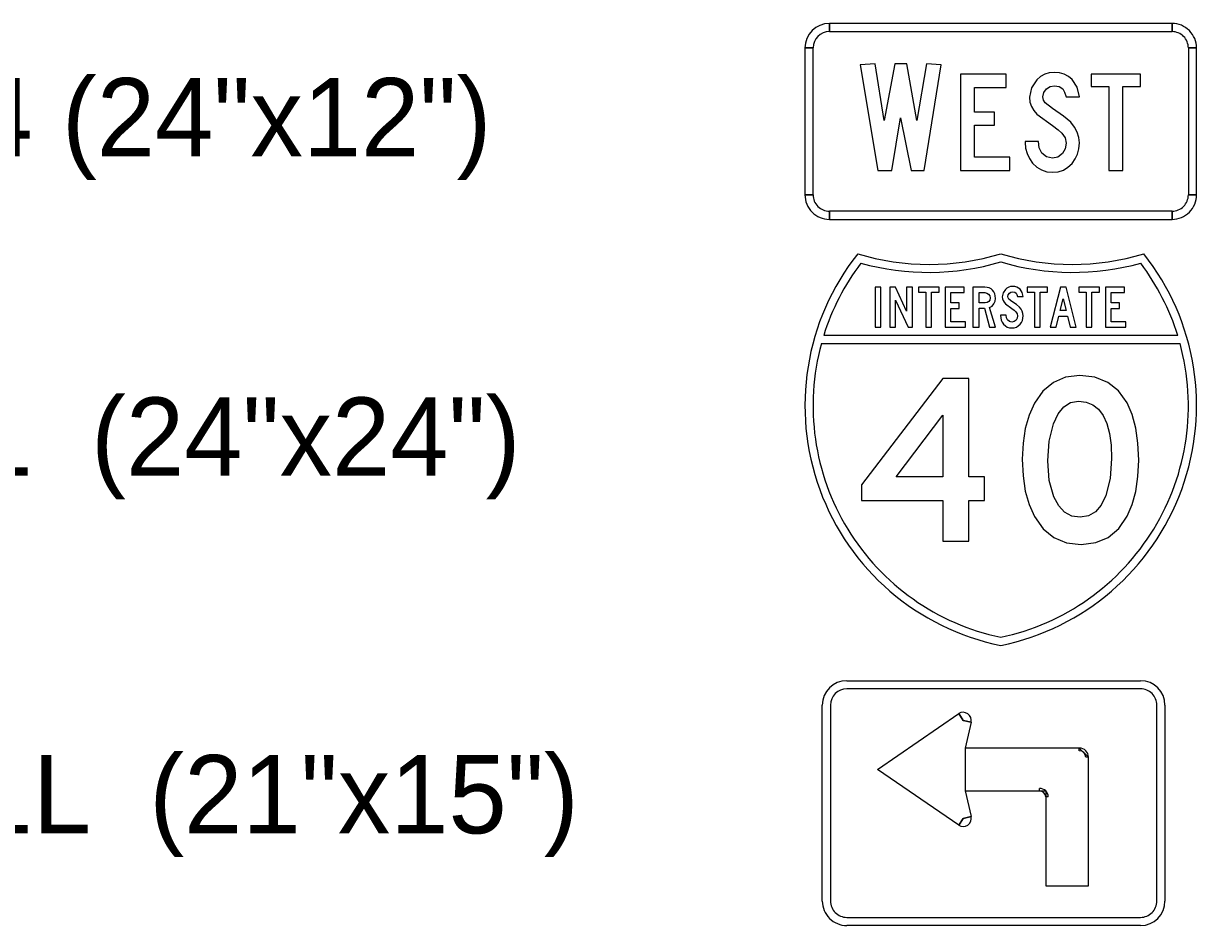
# Model space of a CAD drawing. Extents: x 620864 to 620948.6, y 415499.7 to 415559.1.
# Drawn here: x 620904.04 to 620910.03, y 415510.88 to 415515.48 of the extents above; entities that cross this region are included whole.
import ezdxf

# ---------------------------------------------------------------- set-up
doc = ezdxf.new("R2010")
doc.units = 0
doc.layers.add('SIGNS', color=7, linetype='Continuous')

msp = doc.modelspace()

# ---------------------------------------------------------------- linework, layer by layer
at = {"layer": 'SIGNS'}
for p, q in [((620908.1576, 415515.4409), (620908.1576, 415515.4826)), ((620909.9076, 415515.4826), (620909.9076, 415515.4409)), ((620908.0326, 415515.3576), (620908.0743, 415515.3576)), ((620909.991, 415515.3576), (620910.0326, 415515.3576)), ((620908.0743, 415514.6076), (620908.0326, 415514.6076)), ((620910.0326, 415514.6076), (620909.991, 415514.6076)), ((620908.1576, 415514.4826), (620908.1576, 415514.5243)), ((620909.9076, 415514.5243), (620909.9076, 415514.4826)), ((620908.4208, 415514.1363), (620908.392, 415514.1363)), ((620908.392, 415514.1363), (620908.392, 415513.932)), ((620908.4208, 415513.932), (620908.4208, 415514.1363)), ((620908.495, 415514.1363), (620908.467, 415514.1363)), ((620908.467, 415514.1363), (620908.467, 415513.932)), ((620908.5511, 415514.0144), (620908.495, 415514.1363)), ((620908.5824, 415514.1363), (620908.5511, 415514.1363)), ((620908.5511, 415514.1363), (620908.5511, 415514.0144)), ((620908.5824, 415513.932), (620908.5824, 415514.1363)), ((620908.7179, 415514.1363), (620908.6128, 415514.1363)), ((620908.6128, 415514.1363), (620908.6128, 415514.1106)), ((620908.7179, 415514.1106), (620908.7179, 415514.1363)), ((620908.8455, 415514.1363), (620908.7482, 415514.1363)), ((620908.7482, 415514.1363), (620908.7482, 415513.932)), ((620908.8455, 415514.1083), (620908.8455, 415514.1363)), ((620909.0643, 415514.1314), (620909.0563, 415514.1245)), ((620909.0732, 415514.1364), (620909.0643, 415514.1314)), ((620909.0828, 415514.1393), (620909.0732, 415514.1364)), ((620909.0932, 415514.1403), (620909.0828, 415514.1393)), ((620909.1044, 415514.1394), (620909.0932, 415514.1403)), ((620909.1146, 415514.1366), (620909.1044, 415514.1394)), ((620909.1235, 415514.132), (620909.1146, 415514.1366)), ((620909.1315, 415514.1256), (620909.1235, 415514.132)), ((620909.2721, 415514.1363), (620909.167, 415514.1363)), ((620909.167, 415514.1363), (620909.167, 415514.1106)), ((620909.2721, 415514.1106), (620909.2721, 415514.1363)), ((620909.5367, 415514.1363), (620909.4316, 415514.1363)), ((620909.4316, 415514.1363), (620909.4316, 415514.1106)), ((620909.5367, 415514.1106), (620909.5367, 415514.1363)), ((620909.6643, 415514.1363), (620909.567, 415514.1363)), ((620909.567, 415514.1363), (620909.567, 415513.932)), ((620909.6643, 415514.1083), (620909.6643, 415514.1363)), ((620908.495, 415513.932), (620908.495, 415514.07)), ((620908.495, 415514.07), (620908.5595, 415513.932)), ((620908.6128, 415514.1106), (620908.6501, 415514.1106)), ((620908.6501, 415514.1106), (620908.6501, 415513.932)), ((620908.6798, 415513.932), (620908.6798, 415514.1106)), ((620908.6798, 415514.1106), (620908.7179, 415514.1106)), ((620908.7781, 415514.0562), (620908.7781, 415514.1083)), ((620908.7781, 415514.1083), (620908.8455, 415514.1083)), ((620909.0447, 415514.1074), (620909.0408, 415514.0875)), ((620909.0408, 415514.0875), (620909.0418, 415514.0772)), ((620909.0418, 415514.0772), (620909.0447, 415514.0678)), ((620909.0563, 415514.1245), (620909.0447, 415514.1074)), ((620909.0692, 415514.0883), (620909.0711, 415514.0974)), ((620909.0704, 415514.0815), (620909.0692, 415514.0883)), ((620909.0738, 415514.0755), (620909.0704, 415514.0815)), ((620909.0711, 415514.0974), (620909.0766, 415514.1051)), ((620909.0895, 415514.0638), (620909.0738, 415514.0755)), ((620909.0766, 415514.1051), (620909.0845, 415514.1103)), ((620909.0845, 415514.1103), (620909.094, 415514.1121)), ((620909.094, 415514.1121), (620909.1041, 415514.1104)), ((620909.1041, 415514.1104), (620909.1115, 415514.1055)), ((620909.1115, 415514.1055), (620909.1155, 415514.0986)), ((620909.1155, 415514.0986), (620909.1185, 415514.0883)), ((620909.1185, 415514.0883), (620909.1469, 415514.0883)), ((620909.1423, 415514.1092), (620909.1315, 415514.1256)), ((620909.1469, 415514.0883), (620909.1423, 415514.1092)), ((620909.167, 415514.1106), (620909.2043, 415514.1106)), ((620909.2043, 415514.1106), (620909.2043, 415513.932)), ((620909.234, 415513.932), (620909.234, 415514.1106)), ((620909.234, 415514.1106), (620909.2721, 415514.1106)), ((620909.4316, 415514.1106), (620909.4689, 415514.1106)), ((620909.4689, 415514.1106), (620909.4689, 415513.932)), ((620909.4985, 415513.932), (620909.4985, 415514.1106)), ((620909.4985, 415514.1106), (620909.5367, 415514.1106)), ((620909.5969, 415514.0562), (620909.5969, 415514.1083)), ((620909.5969, 415514.1083), (620909.6643, 415514.1083)), ((620908.8208, 415514.0562), (620908.7781, 415514.0562)), ((620908.7781, 415513.96), (620908.7781, 415514.0281)), ((620908.7781, 415514.0281), (620908.8208, 415514.0281)), ((620908.8208, 415514.0281), (620908.8208, 415514.0562)), ((620909.0447, 415514.0678), (620909.0496, 415514.0591)), ((620909.0496, 415514.0591), (620909.0565, 415514.0512)), ((620909.0565, 415514.0512), (620909.0897, 415514.0275)), ((620909.1132, 415514.0475), (620909.0895, 415514.0638)), ((620909.0897, 415514.0275), (620909.102, 415514.0181)), ((620909.102, 415514.0181), (620909.1096, 415514.0112)), ((620909.1096, 415514.0112), (620909.1164, 415514.001)), ((620909.1286, 415514.0342), (620909.1132, 415514.0475)), ((620909.1366, 415514.0241), (620909.1286, 415514.0342)), ((620909.1423, 415514.0135), (620909.1366, 415514.0241)), ((620909.1457, 415514.0022), (620909.1423, 415514.0135)), ((620909.6395, 415514.0562), (620909.5969, 415514.0562)), ((620909.5969, 415513.96), (620909.5969, 415514.0281)), ((620909.5969, 415514.0281), (620909.6395, 415514.0281)), ((620909.6395, 415514.0281), (620909.6395, 415514.0562)), ((620908.8533, 415513.96), (620908.7781, 415513.96)), ((620908.8533, 415513.932), (620908.8533, 415513.96)), ((620909.0598, 415513.9934), (620909.0316, 415513.9934)), ((620909.0316, 415513.9934), (620909.0316, 415513.9915)), ((620909.0316, 415513.9915), (620909.0324, 415513.9791)), ((620909.0324, 415513.9791), (620909.0354, 415513.9675)), ((620909.0354, 415513.9675), (620909.0404, 415513.957)), ((620909.0404, 415513.957), (620909.0474, 415513.9473)), ((620909.0615, 415513.98), (620909.0598, 415513.9934)), ((620909.0672, 415513.9688), (620909.0615, 415513.98)), ((620909.0769, 415513.9605), (620909.0672, 415513.9688)), ((620909.0895, 415513.9577), (620909.0769, 415513.9605)), ((620909.1012, 415513.9602), (620909.0895, 415513.9577)), ((620909.1109, 415513.9677), (620909.1012, 415513.9602)), ((620909.1167, 415513.978), (620909.1109, 415513.9677)), ((620909.1164, 415514.001), (620909.1187, 415513.9901)), ((620909.1187, 415513.9901), (620909.1167, 415513.978)), ((620909.1313, 415513.9467), (620909.1381, 415513.9562)), ((620909.1381, 415513.9562), (620909.143, 415513.9667)), ((620909.143, 415513.9667), (620909.1459, 415513.978)), ((620909.1469, 415513.9904), (620909.1457, 415514.0022)), ((620909.1459, 415513.978), (620909.1469, 415513.9904)), ((620909.6721, 415513.96), (620909.5969, 415513.96)), ((620909.6721, 415513.932), (620909.6721, 415513.96)), ((620909.9365, 415513.8903), (620908.1288, 415513.8903)), ((620908.392, 415513.932), (620908.4208, 415513.932)), ((620908.467, 415513.932), (620908.495, 415513.932)), ((620908.5595, 415513.932), (620908.5824, 415513.932)), ((620908.6501, 415513.932), (620908.6798, 415513.932)), ((620908.7482, 415513.932), (620908.8533, 415513.932)), ((620909.0474, 415513.9473), (620909.0562, 415513.9388)), ((620909.0562, 415513.9388), (620909.0662, 415513.9328)), ((620909.0662, 415513.9328), (620909.0773, 415513.9292)), ((620909.0773, 415513.9292), (620909.0895, 415513.928)), ((620909.0895, 415513.928), (620909.1016, 415513.9291)), ((620909.1016, 415513.9291), (620909.1127, 415513.9327)), ((620909.1127, 415513.9327), (620909.1225, 415513.9385)), ((620909.1225, 415513.9385), (620909.1313, 415513.9467)), ((620909.2043, 415513.932), (620909.234, 415513.932)), ((620909.4689, 415513.932), (620909.4985, 415513.932)), ((620909.567, 415513.932), (620909.6721, 415513.932)), ((620908.2465, 415512.1272), (620909.7465, 415512.1272)), ((620909.7465, 415512.1272), (620909.7465, 415512.1272)), ((620909.7465, 415512.0855), (620908.2465, 415512.0855)), ((620908.1215, 415511.0022), (620908.1215, 415512.0022)), ((620908.1632, 415512.0022), (620908.1632, 415511.0022)), ((620909.8299, 415511.0022), (620909.8299, 415512.0022)), ((620909.8715, 415512.0022), (620909.8715, 415511.0022)), ((620908.8403, 415511.9241), (620908.818, 415511.9593)), ((620908.8809, 415511.9147), (620908.8403, 415511.9241)), ((620909.434, 415511.7697), (620909.434, 415511.7834)), ((620909.481, 415511.7365), (620909.4672, 415511.7365)), ((620909.231, 415511.5647), (620909.231, 415511.5776)), ((620909.2752, 415511.5334), (620909.2622, 415511.5334)), ((620908.8403, 415511.4241), (620908.8809, 415511.4334)), ((620908.818, 415511.3888), (620908.8403, 415511.4241)), ((620908.2465, 415510.9188), (620909.7465, 415510.9188)), ((620909.7465, 415510.8772), (620908.2465, 415510.8772)), ((620908.2465, 415510.8772), (620908.2465, 415510.8772))]:
    msp.add_line(p, q, dxfattribs=at)
for points in [[(620909.9076, 415515.4826), (620908.1576, 415515.4826), (620908.1576, 415515.4409), (620909.9076, 415515.4409), (620909.9076, 415515.4826), (620909.9076, 415515.4826)], [(620908.0326, 415515.3576), (620908.0326, 415514.6076), (620908.0743, 415514.6076), (620908.0743, 415515.3576), (620908.0326, 415515.3576), (620908.0326, 415515.3576)], [(620910.0326, 415514.6076), (620910.0326, 415515.3576), (620909.991, 415515.3576), (620909.991, 415514.6076), (620910.0326, 415514.6076), (620910.0326, 415514.6076)], [(620908.4053, 415514.7326), (620908.4773, 415514.7326), (620908.5216, 415515.0014), (620908.5745, 415514.7326), (620908.6411, 415514.7326), (620908.7289, 415515.272), (620908.6529, 415515.2764), (620908.6049, 415514.9866), (620908.5527, 415515.2764), (620908.4919, 415515.2764), (620908.438, 415514.9866), (620908.3922, 415515.2764), (620908.3156, 415515.272)], [(620909.0789, 415514.7999), (620908.8983, 415514.7999), (620908.8983, 415514.9633), (620909.0007, 415514.9633), (620909.0007, 415515.0306), (620908.8983, 415515.0306), (620908.8983, 415515.1556), (620909.0601, 415515.1556), (620909.0601, 415515.223), (620908.8267, 415515.223), (620908.8267, 415514.7326), (620909.0789, 415514.7326)], [(620909.1577, 415514.8799), (620909.1577, 415514.8754), (620909.1597, 415514.8456), (620909.1668, 415514.8179), (620909.1789, 415514.7925), (620909.1956, 415514.7694), (620909.2168, 415514.749), (620909.2409, 415514.7346), (620909.2673, 415514.7259), (620909.2966, 415514.723), (620909.3258, 415514.7257), (620909.3524, 415514.7342), (620909.3759, 415514.7482), (620909.397, 415514.768), (620909.4133, 415514.7907), (620909.4251, 415514.8158), (620909.4321, 415514.843), (620909.4345, 415514.8727), (620909.4317, 415514.9011), (620909.4234, 415514.9282), (620909.4096, 415514.9537), (620909.3905, 415514.9779), (620909.3535, 415515.0098), (620909.2966, 415515.0488), (620909.2589, 415515.0771), (620909.2508, 415515.0914), (620909.2481, 415515.1077), (620909.2525, 415515.1296), (620909.2656, 415515.1481), (620909.2847, 415515.1606), (620909.3075, 415515.1648), (620909.3317, 415515.1608), (620909.3495, 415515.149), (620909.3591, 415515.1324), (620909.3664, 415515.1078), (620909.4345, 415515.1078), (620909.4234, 415515.1579), (620909.3974, 415515.1973), (620909.3784, 415515.2126), (620909.3569, 415515.2237), (620909.3324, 415515.2303), (620909.3055, 415515.2326), (620909.2805, 415515.2302), (620909.2575, 415515.2231), (620909.2362, 415515.2112), (620909.217, 415515.1947), (620909.189, 415515.1536), (620909.1799, 415515.1058), (620909.1821, 415515.0811), (620909.1892, 415515.0586), (620909.2009, 415515.0377), (620909.2174, 415515.0188), (620909.2971, 415514.9618), (620909.3267, 415514.9393), (620909.345, 415514.9226), (620909.3612, 415514.8981), (620909.3668, 415514.872), (620909.362, 415514.843), (620909.348, 415514.8184), (620909.3248, 415514.8004), (620909.2966, 415514.7943), (620909.2664, 415514.801), (620909.2431, 415514.821), (620909.2294, 415514.8478), (620909.2254, 415514.8799)], [(620909.5842, 415514.7326), (620909.6554, 415514.7326), (620909.6554, 415515.1614), (620909.7469, 415515.1614), (620909.7469, 415515.223), (620909.4947, 415515.223), (620909.4947, 415515.1614), (620909.5842, 415515.1614)], [(620908.1576, 415514.4826), (620909.9076, 415514.4826), (620909.9076, 415514.5243), (620908.1576, 415514.5243), (620908.1576, 415514.4826), (620908.1576, 415514.4826)], [(620908.4028, 415511.6741), (620908.818, 415511.9593), (620908.8403, 415511.9241), (620908.8809, 415511.9147), (620908.8507, 415511.7834), (620908.8507, 415511.5647), (620908.8809, 415511.4334), (620908.8403, 415511.4241), (620908.818, 415511.3888), (620908.4028, 415511.6741), (620908.4028, 415511.6741)], [(620909.2622, 415511.0802), (620909.481, 415511.0802), (620909.481, 415511.7365), (620909.434, 415511.7834), (620908.8507, 415511.7834), (620908.8507, 415511.5647), (620909.231, 415511.5647), (620909.2622, 415511.5647), (620909.2622, 415511.5334), (620909.2622, 415511.0802), (620909.2622, 415511.0802)]]:
    msp.add_lwpolyline(points, close=True, dxfattribs=at)
for points in [[(620908.3021, 415514.307), (620908.3021, 415514.307)], [(620908.3177, 415514.259), (620908.3177, 415514.259)], [(620909.0326, 415514.2653), (620909.0326, 415514.2653)], [(620909.7476, 415514.259), (620909.7476, 415514.259)], [(620909.7632, 415514.307), (620909.7632, 415514.307)], [(620908.922, 415513.932), (620908.922, 415514.0293), (620908.9492, 415514.0293), (620908.976, 415513.932), (620909.0053, 415513.932), (620908.9756, 415514.0327), (620908.9883, 415514.0398), (620908.9979, 415514.0511), (620909.0034, 415514.0642), (620909.0053, 415514.0791), (620909.0044, 415514.0914), (620909.0018, 415514.1024), (620908.9974, 415514.112), (620908.9914, 415514.1203), (620908.9835, 415514.1273), (620908.9741, 415514.1323), (620908.9633, 415514.1353), (620908.9511, 415514.1363), (620908.8899, 415514.1363), (620908.8899, 415513.932), (620908.922, 415513.932)], [(620909.3154, 415513.932), (620909.3292, 415513.9882), (620909.3733, 415513.9882), (620909.3878, 415513.932), (620909.4176, 415513.932), (620909.3661, 415514.1363), (620909.3372, 415514.1363), (620909.2857, 415513.932), (620909.3154, 415513.932)], [(620908.922, 415514.0562), (620908.922, 415514.1083), (620908.9519, 415514.1083), (620908.9624, 415514.1065), (620908.9708, 415514.1012), (620908.9762, 415514.0929), (620908.978, 415514.0821), (620908.9764, 415514.0707), (620908.9717, 415514.0626), (620908.9639, 415514.0578), (620908.9529, 415514.0562), (620908.922, 415514.0562)], [(620909.3364, 415514.0173), (620909.3509, 415514.0766), (620909.3661, 415514.0173), (620909.3364, 415514.0173)], [(620908.1166, 415513.8487), (620908.6591, 415513.8487), (620909.1861, 415513.8487), (620909.9487, 415513.8487)], [(620908.7376, 415512.8392), (620908.8699, 415512.8392), (620908.8699, 415513.0478), (620908.9495, 415513.0478), (620908.9495, 415513.1684), (620908.8699, 415513.1684), (620908.8699, 415513.6696), (620908.7376, 415513.6696), (620908.3214, 415513.1265), (620908.3214, 415513.0478), (620908.7376, 415513.0478), (620908.7376, 415512.8392)], [(620909.4365, 415513.6859), (620909.364, 415513.6769), (620909.3014, 415513.6502), (620909.2482, 415513.6057), (620909.2047, 415513.5437), (620909.1775, 415513.4828), (620909.1582, 415513.4151), (620909.1464, 415513.3401), (620909.1427, 415513.2582), (620909.1464, 415513.1728), (620909.1582, 415513.0953), (620909.1775, 415513.0262), (620909.2047, 415512.9651), (620909.2487, 415512.9028), (620909.3034, 415512.8582), (620909.3683, 415512.8317), (620909.4441, 415512.823), (620909.5182, 415512.8319), (620909.582, 415512.8588), (620909.6355, 415512.9038), (620909.6787, 415512.9669), (620909.7041, 415513.0262), (620909.7224, 415513.0939), (620909.7334, 415513.1694), (620909.7372, 415513.2531), (620909.7334, 415513.3396), (620909.7222, 415513.4172), (620909.7036, 415513.4856), (620909.6776, 415513.5451), (620909.6339, 415513.6065), (620909.5793, 415513.6504), (620909.5133, 415513.6769), (620909.4365, 415513.6859)], [(620909.5986, 415513.262), (620909.5911, 415513.159), (620909.5695, 415513.073), (620909.5462, 415513.0241), (620909.5166, 415512.9893), (620909.4808, 415512.9684), (620909.439, 415512.9616), (620909.3958, 415512.9679), (620909.3591, 415512.9875), (620909.3286, 415513.0198), (620909.3042, 415513.0654), (620909.2806, 415513.1496), (620909.2729, 415513.2503), (620909.2803, 415513.35), (620909.3027, 415513.4388), (620909.3255, 415513.4892), (620909.3544, 415513.5253), (620909.3887, 415513.547), (620909.4291, 415513.5543), (620909.4686, 415513.5498), (620909.5032, 415513.536), (620909.5321, 415513.5131), (620909.5561, 415513.4811), (620909.5744, 415513.4398), (620909.5878, 415513.3897), (620909.5958, 415513.3302), (620909.5986, 415513.262)], [(620908.7376, 415513.1684), (620908.4979, 415513.1684), (620908.7376, 415513.4823), (620908.7376, 415513.1684)], [(620909.0326, 415512.3487), (620909.0326, 415512.3487)], [(620909.0326, 415512.307), (620909.0326, 415512.307)], [(620908.2465, 415512.1272), (620908.2465, 415512.1272)], [(620908.1215, 415512.0022), (620908.1215, 415512.0022)], [(620909.8715, 415511.0022), (620909.8715, 415511.0022)], [(620909.7465, 415510.8772), (620909.7465, 415510.8772)]]:
    msp.add_lwpolyline(points, dxfattribs=at)
for centre, radius, start, end in [((620908.1576, 415515.3576), 0.125, 90.00021, 179.99985), ((620909.9076, 415515.3576), 0.125, 360, 90.00021), ((620908.1576, 415515.3576), 0.0833, 90.00021, 179.99985), ((620909.9076, 415515.3576), 0.0833, 360, 90.00021), ((620908.1576, 415514.6076), 0.125, 179.99985, 270.00006), ((620908.1576, 415514.6076), 0.0833, 179.99985, 270.00006), ((620909.9076, 415514.6076), 0.125, 270.00006, 0.00027), ((620909.9076, 415514.6076), 0.0833, 270.00006, 0.00027), ((620909.2826, 415513.5317), 1.25, 141.66897, 258.46298), ((620909.2824, 415513.5309), 1.2083, 142.99594, 162.69525), ((620908.6673, 415515.5024), 1.25, 253.009, 286.99091), ((620908.6642, 415515.5033), 1.2917, 254.4391, 286.57458), ((620908.7826, 415513.5317), 1.25, 281.53714, 38.33115), ((620909.3979, 415515.5024), 1.25, 253.00909, 286.99112), ((620909.4011, 415515.5033), 1.2917, 253.42554, 285.56102), ((620908.7828, 415513.5309), 1.2083, 17.30466, 37.00414), ((620909.2824, 415513.5309), 1.2083, 164.75344, 258.07036), ((620908.7828, 415513.5309), 1.2083, 281.92964, 15.24668), ((620908.7828, 415513.5309), 1.2083, 281.92961, 281.92964), ((620909.2824, 415513.5309), 1.2083, 258.07036, 258.0705), ((620908.2465, 415512.0022), 0.125, 90.00021, 179.99985), ((620909.7465, 415512.0022), 0.125, 360, 90), ((620908.2465, 415512.0022), 0.0833, 90.00021, 179.99985), ((620909.7465, 415512.0022), 0.0833, 360, 90.00021), ((620908.8403, 415511.9241), 0.0417, 347.04959, 122.27565), ((620909.434, 415511.7365), 0.0469, 0.00015, 89.99979), ((620909.434, 415511.7365), 0.0332, 0.00015, 89.99979), ((620909.231, 415511.5334), 0.0442, 0.00015, 89.99979), ((620909.231, 415511.5334), 0.0312, 0.00015, 89.99979), ((620908.8403, 415511.4241), 0.0417, 237.72408, 12.95014), ((620908.2465, 415511.0022), 0.125, 179.99985, 270), ((620908.2465, 415511.0022), 0.0833, 179.99985, 270.00006), ((620909.7465, 415511.0022), 0.125, 270.00006, 360), ((620909.7465, 415511.0022), 0.0833, 270.00006, 0.00027)]:
    msp.add_arc(centre, radius, start, end, dxfattribs=at)

# ---------------------------------------------------------------- texts
for s, p in [('M3-4 (24"x12")', (620902.871, 415514.804)), ('M1-1  (24"x24")', (620902.871, 415513.1732)), ('M5-1L  (21"x15")', (620902.871, 415511.3476))]:
    msp.add_text(s, height=0.4, rotation=0, dxfattribs=at).set_placement(p)

doc.saveas('drawing.dxf')
